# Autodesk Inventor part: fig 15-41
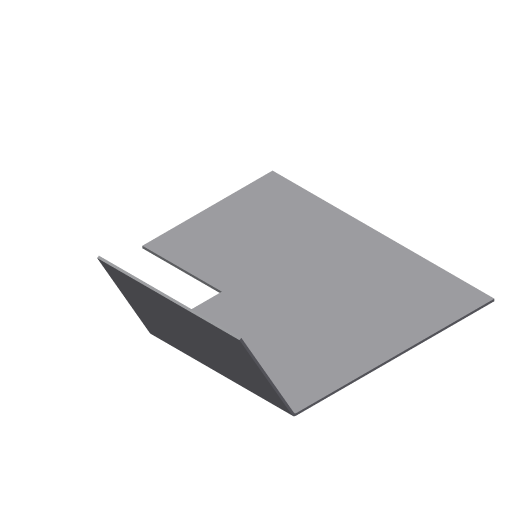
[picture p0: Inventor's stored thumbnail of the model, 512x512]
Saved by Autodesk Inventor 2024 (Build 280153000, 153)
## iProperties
Created: 2005-03
Part Number: fig 15-41
Document SubType Name: Sheet Metal
Designer: CADCIM
Manufacturer: Standard
Standards Organization: Custom
Density: 1 g/cm^3
Sheet Metal Rule: Default
Material: Generic
Appearance: Default
Author: CADCIM
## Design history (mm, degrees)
node "Face1"
  sketch "Sketch1"
    geometry: L1 (31.393, 35.714)-(-19.875, 35.714); L2 (-19.875, 35.714)-(-19.875, 5.625); L3 (-19.875, 5.625)-(-1.5, 5.625); L4 (-1.5, 5.625)-(-1.5, -10.705); L5 (-1.5, -10.705)-(31.393, -10.705); L6 (31.393, -10.705)-(31.393, 35.714)
    constraints: 12 end point, 4 parallel, 1 horizontal, 1 perpendicular
node "Flange1"
body "Solid1"
sketch "Sketch3"
  geometry: L1 (18.375, -30.089)-(18.375, 0); L2 (18.375, -46.42)-(18.375, -30.089) reference; L3 (18.375, -30.089)-(0, -30.089) reference; L4 (0, 0)-(51.268, 0) reference
  constraints: 3 point on line, 2 end point, 1 vertical
face "Plate1" dims "d11" = 0.5 (= Thickness)
sketch "Sketch4"
  geometry: L1 through (-16.446, 0) direction (1, 0); L2 through (0, 12.5) direction (-6.75e-17, 1); L3 (0, 25)-(-32.893, 25); L4 (-32.893, 25)-(-32.893, 0)
  constraints: 6 end point, 1 horizontal, 1 perpendicular, 1 vertical
face "Plate2" dims "d1" = 0.5 (= BendReliefWidth), "d2" = 0.25 (= BendReliefDepth), "d3" = 1 (= MinimumRemnant), "d4" = 0.5 (= BendRadius), "d5" = 25, "d6" = 60 deg, "d7" = 0.5 (= BendRadius), "d8" = 2 (= CornerReliefSize), "d9" = 0.5 (= GapSize), "d10" = 0.5 (= JacobiRadiusSize), "d11" = 0.5 (= Thickness), "SeamGap" = 0.01
bend "Bend1" dims "d1" = 0.5 (= BendReliefWidth), "d2" = 0.25 (= BendReliefDepth), "d3" = 1 (= MinimumRemnant), "d4" = 0.5 (= BendRadius), "d5" = 25, "d6" = 60 deg, "d7" = 0.5 (= BendRadius), "d11" = 0.5 (= Thickness), "SeamGap" = 0.01
feature "Corner1" dims "d5" = 25, "d6" = 60 deg, "d8" = 2 (= CornerReliefSize), "d9" = 0.5 (= GapSize), "d10" = 0.5 (= JacobiRadiusSize)
other parameters: "Thickness" = 0.5, "BendRadius" = 0.5 (= Thickness), "BendReliefWidth" = 0.5 (= Thickness), "BendReliefDepth" = 0.25 (= 0.5 x Thickness), "CornerReliefSize" = 2 (= 4 x Thickness), "MinimumRemnant" = 1 (= 2 x Thickness), "TransitionRadius" = 0.5 (= BendRadius), "d0" = 0.5 (= BendRadius), "JacobiRadiusSize" = 0.5 (= Thickness), "GapSize" = 0.5 (= Thickness)
